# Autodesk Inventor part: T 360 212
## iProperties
Shininess: 64.0
Angle Display Precision: 2
Document Length Units: 11269
Document Angle Units: 11279
Document Time Units: 11290
Document Mass Units: 11283
Document Length Units Precision: 3
Document Angle Units Precision: 2
Compacted: True
Created: 2001-11
Part Number: T 360 212
Document SubType Name: Modeling
Designer: I.Baliuc
Material: 1.1200
Description: Druckfeder
Vendor: GUTERKUNST
Density: 7.84 g/cm^3
Density: 0.0
Volumn: 0.0
Area: 0.0
PropertySet Name: Model Information
Control State: 0
Master: False
Checked Out: False
HalbzeugNorm: VD-288S
Zweck: für Vorkontakt
Abmessung: 2.8 x 20.0 - 101
Author: T.Messerschmitt
Revision Number: 360212
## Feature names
1. Trennen1
2. Bezeichnung2 [Tagging]
